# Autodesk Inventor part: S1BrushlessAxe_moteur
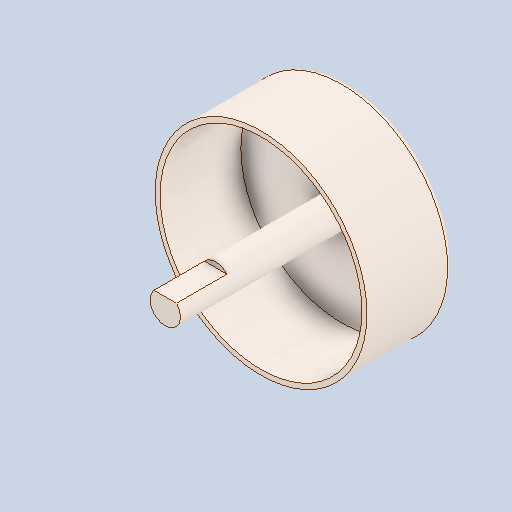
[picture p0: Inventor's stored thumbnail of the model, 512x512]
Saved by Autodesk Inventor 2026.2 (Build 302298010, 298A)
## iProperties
Created: 1601-01
Part Number: S1BrushlessAxe_moteur
Material: 201 Annealed Stainless Steel (SS)
Document SubType Name: Modeling
Designer: mel
Density: 7.86 g/cm^3
Appearance: satin finish stainless steel
Author: mel
Sending System: SOLIDWORKS 2023
Part Number: Axe_moteur
Last Saved Date: 2025-04-02
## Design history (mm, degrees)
feature "Congé1"
node "Solide1"
